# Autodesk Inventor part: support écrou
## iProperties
Shininess: 64.0
Length Units: 11269
Angle Units: 11279
Time Units: 11290
Mass Units: 11283
Length Display Precision: 3
Angle Display Precision: 2
Compacted: True
Part Number: support écrou
Document SubType Name: Modeling
Created: 2005-02
Material: Par défaut
Designer: LEGERET Philippe
Density: 0.0
Volumn: 0.0
Area: 0.0
PropertySet Name: Model Information
Control State: 0
Master: False
Checked Out: False
Author: LEGERET Philippe
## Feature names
1. Extrusion1
2. Perçage1 [Hole]
3. Chanfrein1 [Chamfer]
4. Perçage2 [Hole]
5. Réseau circulaire1 [Circular Pattern]
